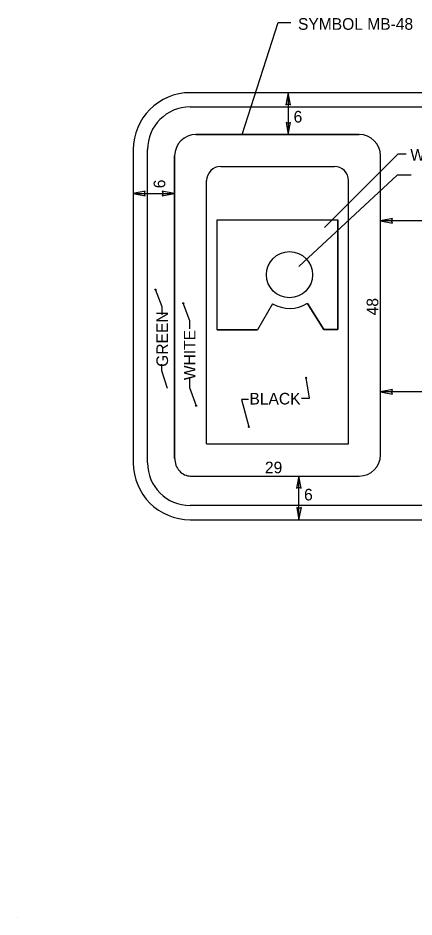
# Model space of a CAD drawing. Extents: x 60712 to 61344, y 9358 to 10016.
# Drawn here: x 60711.7 to 60817.5, y 9358 to 9598 of the extents above; entities that cross this region are included whole.
import ezdxf

# ---------------------------------------------------------------- set-up
doc = ezdxf.new("R2010")
doc.units = 0
for name, color, linetype in [('1', 7, 'Continuous'), ('52', 7, 'Continuous'), ('AdhocPoint_dp', 7, 'Continuous'), ('SignPanel', 7, 'Continuous')]:
    doc.layers.add(name, color=color, linetype=linetype)

msp = doc.modelspace()

# ---------------------------------------------------------------- linework, layer by layer
at = {"layer": '1'}
for p, q in [((60771.58, 9566.95), (60781.18, 9596.8)), ((60781.18, 9596.8), (60784.62, 9596.8)), ((60813.16, 9561.67), (60793.55, 9542.12)), ((60815.37, 9561.67), (60813.16, 9561.67)), ((60813.02, 9556.05), (60786.75, 9531.7)), ((60816.74, 9556.05), (60813.02, 9556.05)), ((60750.2, 9520.96), (60748.41, 9525.52)), ((60757.63, 9517.16), (60755.84, 9521.87)), ((60750.2, 9518.83), (60750.2, 9520.96)), ((60757.63, 9515.04), (60757.63, 9517.16)), ((60750.06, 9505.59), (60750.06, 9503.95)), ((60750.06, 9503.95), (60751.57, 9499.24)), ((60789.54, 9496.52), (60788.71, 9501.99)), ((60757.49, 9501.82), (60757.49, 9499.39)), ((60757.49, 9499.39), (60759.28, 9494.53)), ((60773.24, 9496.22), (60771.45, 9496.22)), ((60771.45, 9496.22), (60773.38, 9488.92)), ((60787.47, 9496.52), (60789.54, 9496.52))]:
    msp.add_line(p, q, dxfattribs=at)
for centre in [(60748.41, 9525.52), (60755.84, 9521.87), (60788.71, 9501.99), (60759.28, 9494.53), (60773.38, 9488.92)]:
    msp.add_ellipse(centre, major_axis=(0, 0.157), ratio=0.906668, dxfattribs=at)
at = {"layer": '52'}
for p, q in [((60783.91, 9578.1), (60783.29, 9574.88)), ((60784.51, 9574.88), (60783.91, 9578.1)), ((60783.29, 9574.88), (60783.91, 9575.12)), ((60783.91, 9575.12), (60784.51, 9574.88)), ((60783.91, 9569.9), (60783.31, 9570.14)), ((60783.31, 9570.14), (60783.91, 9566.92)), ((60783.91, 9566.92), (60784.53, 9570.14)), ((60784.53, 9570.14), (60783.91, 9569.9)), ((60745.72, 9551.8), (60742.5, 9551.2)), ((60742.5, 9551.2), (60745.72, 9550.58)), ((60745.48, 9551.2), (60745.72, 9551.8)), ((60745.72, 9550.58), (60745.48, 9551.2)), ((60753.43, 9551.2), (60750.21, 9551.82)), ((60750.21, 9551.82), (60750.45, 9551.2)), ((60750.45, 9551.2), (60750.21, 9550.6)), ((60750.21, 9550.6), (60753.43, 9551.2)), ((60811.75, 9544.5), (60808.53, 9543.9)), ((60808.53, 9543.9), (60811.75, 9543.28)), ((60811.51, 9543.9), (60811.75, 9544.5)), ((60811.75, 9543.28), (60811.51, 9543.9)), ((60811.75, 9498.88), (60808.53, 9498.28)), ((60808.53, 9498.28), (60811.75, 9497.66)), ((60811.51, 9498.28), (60811.75, 9498.88)), ((60811.75, 9497.66), (60811.51, 9498.28)), ((60786.76, 9475.76), (60786.14, 9472.54)), ((60787.36, 9472.54), (60786.76, 9475.76)), ((60786.14, 9472.54), (60786.76, 9472.78)), ((60786.76, 9472.78), (60787.36, 9472.54)), ((60786.76, 9467.08), (60786.16, 9467.32)), ((60786.16, 9467.32), (60786.76, 9464.1)), ((60786.76, 9464.1), (60787.39, 9467.32)), ((60787.39, 9467.32), (60786.76, 9467.08))]:
    msp.add_line(p, q, dxfattribs=at)
at = {"layer": 'AdhocPoint_dp'}
msp.add_line((60711.71, 9358.04), (60711.71, 9358.04), dxfattribs=at)
at = {"layer": 'SignPanel'}
for p, q in [((61000.9, 9578.1), (60757.7, 9578.1)), ((60783.91, 9578.1), (60783.91, 9566.92)), ((60757.7, 9574.3), (61000.9, 9574.3)), ((60759.25, 9566.94), (60802.85, 9566.94)), ((60802.85, 9566.94), (60759.25, 9566.94)), ((60742.5, 9562.9), (60742.5, 9479.3)), ((60746.3, 9479.3), (60746.3, 9562.9)), ((60753.56, 9480.46), (60753.56, 9561.26)), ((60753.56, 9561.26), (60753.56, 9480.46)), ((60808.53, 9481.44), (60808.53, 9561.26)), ((60808.53, 9481.44), (60808.53, 9561.26)), ((60765.88, 9558.42), (60765.88, 9558.41)), ((60765.88, 9558.41), (60796.21, 9558.41)), ((60762.09, 9484.38), (60762.09, 9554.62)), ((60800, 9484.38), (60800, 9554.62)), ((60742.5, 9551.2), (60753.43, 9551.2)), ((60764.94, 9514.82), (60764.94, 9544.2)), ((60764.94, 9544.2), (60797.16, 9544.2)), ((60764.94, 9514.82), (60764.94, 9544.2)), ((60764.94, 9544.2), (60797.16, 9544.2)), ((60797.16, 9514.85), (60797.16, 9544.2)), ((60797.16, 9544.2), (60797.16, 9514.85)), ((60849.48, 9543.9), (60808.53, 9543.9)), ((60779.7, 9521.74), (60775.66, 9514.82)), ((60779.7, 9521.74), (60775.66, 9514.82)), ((60789, 9521.86), (60793.37, 9514.85)), ((60793.37, 9514.85), (60789, 9521.86)), ((60764.94, 9514.82), (60775.66, 9514.82)), ((60775.66, 9514.82), (60764.94, 9514.82)), ((60793.37, 9514.85), (60797.16, 9514.85)), ((60797.16, 9514.85), (60793.37, 9514.85)), ((60850.44, 9498.28), (60808.53, 9498.28)), ((60762.09, 9484.38), (60800, 9484.38)), ((60757.83, 9475.76), (60757.83, 9475.75)), ((60757.83, 9475.75), (60802.85, 9475.75)), ((60757.83, 9475.75), (60802.85, 9475.75)), ((60786.76, 9464.1), (60786.76, 9475.76)), ((61000.9, 9467.9), (60757.74, 9467.9)), ((60757.74, 9464.1), (61000.9, 9464.1))]:
    msp.add_line(p, q, dxfattribs=at)
msp.add_circle((60784.24, 9529.51), 6.16, dxfattribs=at)
for centre, radius, start, end in [((60757.7, 9562.9), 15.2, 90, 180), ((60757.7, 9562.9), 11.4, 90, 180), ((60759.25, 9561.26), 5.69, 90, 180), ((60759.25, 9561.26), 5.69, 90, 180), ((60802.84, 9561.26), 5.69, 0, 90), ((60802.84, 9561.26), 5.69, 0, 90), ((60765.88, 9554.63), 3.79, 90, 180), ((60796.21, 9554.63), 3.79, 0, 90), ((60784.24, 9529.51), 9, 239.7206, 301.9049), ((60784.24, 9529.51), 9, 239.7206, 301.9049), ((60802.84, 9481.44), 5.69, 270, 360), ((60802.84, 9481.44), 5.69, 270, 360), ((60757.7, 9479.3), 15.2, 180, 270), ((60757.7, 9479.3), 11.4, 180, 270)]:
    msp.add_arc(centre, radius, start, end, dxfattribs=at)
msp.add_ellipse((60757.83, 9480.46), major_axis=(0, 4.7), ratio=0.906668, start_param=1.570796, end_param=3.141593, dxfattribs=at)
msp.add_ellipse((60757.83, 9480.46), major_axis=(0, 4.7), ratio=0.906668, start_param=1.570796, end_param=3.141593, dxfattribs=at)

# ---------------------------------------------------------------- texts
at = {"layer": '1'}
for s, height, p in [('SYMBOL MB-48', 3.1111, (60786.5, 9594.89)), ('WHITE', 3.111, (60816.49, 9559.98)), ('BLACK', 3.111, (60773.53, 9494.86)), ('29', 3.111, (60777.67, 9476.49))]:
    msp.add_text(s, height=height, dxfattribs=at).set_placement(p)
for s, p in [('48', (60807.94, 9518.66)), ('GREEN', (60751.79, 9504.91)), ('WHITE', (60759.12, 9501.36))]:
    msp.add_text(s, height=3.111, rotation=90, dxfattribs=at).set_placement(p)
at = {"layer": 'SignPanel'}
for p in [(60785.33, 9570.13), (60788.12, 9469.25)]:
    msp.add_text('6', height=3.11, dxfattribs=at).set_placement(p)
msp.add_text('6', height=3.11, rotation=90, dxfattribs=at).set_placement((60751.05, 9552.58))

doc.saveas('drawing.dxf')
